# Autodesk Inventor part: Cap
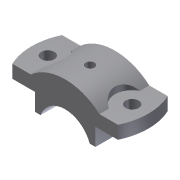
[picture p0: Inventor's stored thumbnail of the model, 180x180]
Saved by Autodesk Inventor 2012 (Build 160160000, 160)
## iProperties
Created: 2009-04
Part Number: Cap
Document SubType Name: Modeling
Designer: Sham
Density: 1 g/cm^3
Material: Default
Author: Sham
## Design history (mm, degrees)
sketch "Sketch1"
  geometry: L1 (-48.857, 23)-(48.857, 23); L2 (48.857, -23)-(-48.857, -23); A1 r 54 centre (0, 0) between (-48.857, 23) and (-48.857, -23); A2 r 54 centre (0, 0) between (48.857, -23) and (48.857, 23); 1 further point
  constraints: 4 end point, 4 point on circle, 2 centre point, 2 coincident, 1 horizontal, 1 parallel, 1 other
  dimensions: "d3" = 54 radius of A1; "d4" = 54 radius of A2; "d5" = 46 distance between parallel lines of L2 L1; "d6" = 23 distance from line of point (0, 0) L1
extrude "Extrusion1" new body sketch "Sketch1" distance "d7" = 12; taper "d8" = 0 deg
sketch "Sketch3"
  geometry: L1 (20.906, 0)-(20.906, -16); L2 (76.906, -0.137)-(76.906, -16.137); L3 (20.906, -16)-(26.23, -16); L4 (71.532, -16.137)-(76.906, -16.137); L5 (76.906, -0.137)-(76.857, 12); L6 (97.714, 0)-(0, 0) reference; L7 (76.857, 12)-(80.606, 12); L8 (17.108, 12)-(20.906, 12); L9 (20.906, 12)-(20.906, 0); L10 (0, 12)-(97.714, 12) reference; A1 r 24 centre (48.857, -24) between (71.532, -16.137) and (26.23, -16); A2 r 48 centre (48.857, -24) between (80.606, 12) and (17.108, 12); 3 further points
  constraints: 16 end point, 4 point on circle, 3 parallel, 3 perpendicular, 2 centre point, 2 coincident, 2 vertical alignment, 1 collinear, 1 midpoint, 1 vertical, 2 other
  dimensions: "d17" = 48 diameter of A1; "d18" = 16 distance of L1.start L1.end; "d19" = 56 distance between parallel lines of L2 L1; "d21" = 8 vertical distance of A1.centre L1.end; "d22" = 48 radius of A2; "d23" = 0 distance from line of L6 L1.start; "d38" = 31.74902 distance of L7.end point (48.857, 12); "d39" = 28 distance from line of point (48.857, 12) L5
extrude "Extrusion2" join sketch "Sketch3" stored distance "d24" = 12; taper "d25" = 0 deg
sketch "Sketch4"
  geometry: 2 further points
  dimensions: "d26" = 78 distance of point (39, 0) point (-39, 0)
hole "Hole1" sketch "Sketch4" at (-39, 0), (39, 0) diameter "d28" = 12; stored, may be unused: countersink angle "d32" = 90 deg, drill point angle "d34" = 118 deg; dims "d29" = 6, "d30" = 4, "d31" = 2, "d33" = 8
sketch "Sketch5"
  geometry: L1 (-31.749, -23)-(-31.749, 23) reference; L2 (-31.749, 14.263)-(-31.749, -14.263); C1 r 6 at (-39, 0) reference; A1 r 16 centre (-39, 0) between (-31.749, -14.263) and (-31.749, 14.263)
  constraints: 2 end point, 2 point on circle, 1 centre point, 1 coincident, 1 collinear, 1 point on line
  dimensions: "d35" = 16 radius of A1
extrude "Extrusion3" cut sketch "Sketch5" distance "d36" = 12; taper "d37" = 0 deg
mirror "Mirror2"
workplane "Work Plane4"
sketch "Sketch6"
  geometry: L1 (-31.749, 0)-(31.749, 0) reference; 1 further point
  dimensions: "d40" = 23 distance from line of L1 point (0, 23)
hole "Hole2" sketch "Sketch6" at (0, 23) diameter "d41" = 6; stored, may be unused: countersink angle "d45" = 90 deg, drill point angle "d47" = 118 deg; dims "d42" = 6, "d43" = 8, "d44" = 16, "d46" = 8
body "Solid1"
